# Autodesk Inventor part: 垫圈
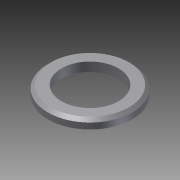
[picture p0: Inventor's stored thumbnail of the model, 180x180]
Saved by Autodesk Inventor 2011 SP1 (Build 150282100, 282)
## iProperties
Created: 2013-11
Part Number: 垫圈
Document SubType Name: Modeling
Designer: Administrator
Density: 1 g/cm^3
Author: Administrator
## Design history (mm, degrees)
sketch "草图1"
  geometry: C1 r 14 at (0, 0); 1 further point
  constraints: 1 centre point, 1 coincident
  dimensions: "d0" = 28 diameter of C1
extrude "拉伸1" new body sketch "草图1" distance "d1" = 3; taper "d2" = 0 deg
hole "Hole1" diameter "d5" = 19; stored, may be unused: countersink angle "d9" = 90 deg, drill point angle "d11" = 0 deg; dims "d3" = 10, "d4" = 10, "d6" = 6, "d7" = 4, "d8" = 2, "d10" = 8
chamfer "倒角1" distance "d12" = 1; stored, may be unused: second distance "d13" = 2, angle "d14" = 45 deg
node "实体1"
